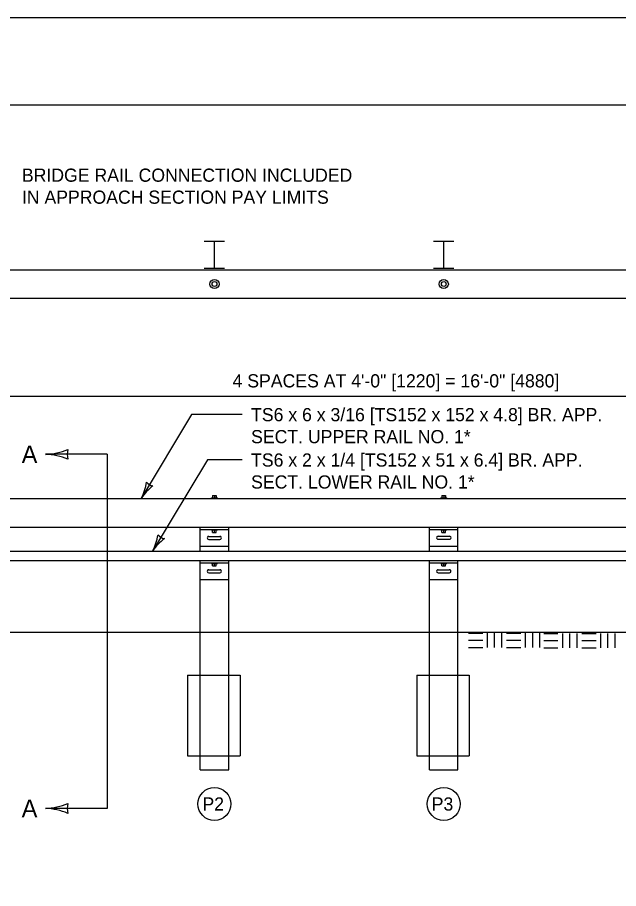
# Model space of a CAD drawing. Extents: x 49991.4 to 50021, y 49987.6 to 50011.4.
# Drawn here: x 50002.258 to 50004.991, y 49995.037 to 49998.999 of the extents above; entities that cross this region are included whole.
import ezdxf

# ---------------------------------------------------------------- set-up
doc = ezdxf.new("R2010")
doc.units = 0
for name, color, linetype in [('Level 1', 7, 'Continuous'), ('Level 2', 7, 'Continuous'), ('Level 3', 7, 'Continuous'), ('Level 4', 7, 'Continuous'), ('Level 6', 7, 'Continuous')]:
    doc.layers.add(name, color=color, linetype=linetype)

msp = doc.modelspace()

# ---------------------------------------------------------------- linework, layer by layer
at = {"layer": 'Level 1'}
for p, q in [((50003.1077, 49997.982), (50003.1991, 49997.982)), ((50003.1539, 49997.8587), (50003.1539, 49997.982)), ((50004.1503, 49997.982), (50004.2425, 49997.982)), ((50004.1964, 49997.8587), (50004.1964, 49997.982)), ((50001.743, 49997.8514), (50015.4519, 49997.8514)), ((50003.1077, 49997.8587), (50003.1991, 49997.8587)), ((50004.1503, 49997.8587), (50004.2425, 49997.8587)), ((50001.743, 49997.7218), (50015.4519, 49997.7218)), ((50002.0298, 49996.8116), (50015.4519, 49996.8116)), ((50003.1396, 49996.8144), (50003.1681, 49996.8144)), ((50003.1396, 49996.8116), (50003.1396, 49996.8144)), ((50003.1451, 49996.825), (50003.161, 49996.825)), ((50003.1451, 49996.825), (50003.1451, 49996.8144)), ((50003.1539, 49996.825), (50003.1539, 49996.8144)), ((50003.161, 49996.825), (50003.161, 49996.8144)), ((50003.1681, 49996.8116), (50003.1681, 49996.8144)), ((50004.1314, 49996.8116), (50004.2611, 49996.8116)), ((50004.1829, 49996.8144), (50004.2106, 49996.8144)), ((50004.1829, 49996.8116), (50004.1829, 49996.8144)), ((50004.1883, 49996.825), (50004.2044, 49996.825)), ((50004.1883, 49996.825), (50004.1883, 49996.8144)), ((50004.1964, 49996.825), (50004.1964, 49996.8144)), ((50004.2044, 49996.825), (50004.2044, 49996.8144)), ((50004.2106, 49996.8116), (50004.2106, 49996.8144)), ((50002.0298, 49996.6812), (50015.4519, 49996.6812)), ((50003.0882, 49996.5719), (50003.0882, 49996.6812)), ((50003.0882, 49996.6705), (50003.2188, 49996.6705)), ((50003.1396, 49996.6705), (50003.1396, 49996.6679)), ((50003.1396, 49996.6679), (50003.1681, 49996.6679)), ((50003.1451, 49996.6572), (50003.1451, 49996.6679)), ((50003.1451, 49996.6572), (50003.161, 49996.6572)), ((50003.1539, 49996.6572), (50003.1539, 49996.6679)), ((50003.161, 49996.6572), (50003.161, 49996.6679)), ((50003.1681, 49996.6705), (50003.1681, 49996.6679)), ((50003.2188, 49996.5719), (50003.2188, 49996.6812)), ((50004.1314, 49996.5719), (50004.1314, 49996.6812)), ((50004.1314, 49996.6705), (50004.2611, 49996.6705)), ((50004.1829, 49996.6705), (50004.1829, 49996.6679)), ((50004.1829, 49996.6679), (50004.2106, 49996.6679)), ((50004.1883, 49996.6572), (50004.1883, 49996.6679)), ((50004.1883, 49996.6572), (50004.2044, 49996.6572)), ((50004.1964, 49996.6572), (50004.1964, 49996.6679)), ((50004.2044, 49996.6572), (50004.2044, 49996.6679)), ((50004.2106, 49996.6705), (50004.2106, 49996.6679)), ((50004.2611, 49996.5719), (50004.2611, 49996.6812)), ((50003.127, 49996.6389), (50003.1793, 49996.6389)), ((50003.1279, 49996.6253), (50003.1785, 49996.6253)), ((50004.1714, 49996.6397), (50004.2238, 49996.6397)), ((50004.1714, 49996.6261), (50004.2221, 49996.6261)), ((50002.0449, 49996.5719), (50012.5032, 49996.5719)), ((50003.0882, 49996.595), (50003.2188, 49996.595)), ((50004.1314, 49996.595), (50004.2611, 49996.595)), ((50002.0449, 49996.5294), (50007.0485, 49996.5294)), ((50003.0882, 49996.2026), (50003.0882, 49996.5294)), ((50003.2188, 49996.2026), (50003.2188, 49996.5294)), ((50004.1314, 49996.2026), (50004.1314, 49996.5294)), ((50004.2611, 49996.2026), (50004.2611, 49996.5294)), ((50003.0882, 49996.5187), (50003.2188, 49996.5187)), ((50003.1396, 49996.5187), (50003.1396, 49996.5152)), ((50003.1396, 49996.5152), (50003.1681, 49996.5152)), ((50003.1451, 49996.5044), (50003.1451, 49996.5152)), ((50003.1451, 49996.5044), (50003.161, 49996.5044)), ((50003.1539, 49996.5044), (50003.1539, 49996.5152)), ((50003.161, 49996.5044), (50003.161, 49996.5152)), ((50003.1681, 49996.5187), (50003.1681, 49996.5152)), ((50004.1314, 49996.5187), (50004.2611, 49996.5187)), ((50004.1829, 49996.5187), (50004.1829, 49996.5152)), ((50004.1829, 49996.5152), (50004.2106, 49996.5152)), ((50004.1883, 49996.5044), (50004.1883, 49996.5152)), ((50004.1883, 49996.5044), (50004.2044, 49996.5044)), ((50004.1964, 49996.5044), (50004.1964, 49996.5152)), ((50004.2044, 49996.5044), (50004.2044, 49996.5152)), ((50004.2106, 49996.5187), (50004.2106, 49996.5152)), ((50003.127, 49996.4868), (50003.1793, 49996.4868)), ((50003.1279, 49996.4732), (50003.1785, 49996.4732)), ((50004.17, 49996.4868), (50004.2224, 49996.4868)), ((50004.1714, 49996.4734), (50004.2221, 49996.4734)), ((50003.0882, 49996.4422), (50003.2188, 49996.4422)), ((50004.1314, 49996.4422), (50004.2611, 49996.4422)), ((50001.5626, 49996.2026), (50015.4519, 49996.2026)), ((50004.3084, 49996.1988), (50004.3734, 49996.1988)), ((50004.3951, 49996.1338), (50004.3951, 49996.1988)), ((50004.4276, 49996.1338), (50004.4276, 49996.1988)), ((50004.4601, 49996.1338), (50004.4601, 49996.1988)), ((50004.4817, 49996.1988), (50004.5468, 49996.1988)), ((50004.5685, 49996.1338), (50004.5685, 49996.1988)), ((50004.6009, 49996.1338), (50004.6009, 49996.1988)), ((50004.6334, 49996.1338), (50004.6334, 49996.1988)), ((50004.6508, 49996.1974), (50004.7158, 49996.1974)), ((50004.7375, 49996.1324), (50004.7375, 49996.1974)), ((50004.77, 49996.1324), (50004.77, 49996.1974)), ((50004.8025, 49996.1324), (50004.8025, 49996.1974)), ((50004.8241, 49996.1974), (50004.8892, 49996.1974)), ((50004.9109, 49996.1324), (50004.9109, 49996.1974)), ((50004.9433, 49996.1324), (50004.9433, 49996.1974)), ((50004.9758, 49996.1324), (50004.9758, 49996.1974)), ((50004.3084, 49996.1663), (50004.3734, 49996.1663)), ((50004.3084, 49996.1338), (50004.3734, 49996.1338)), ((50004.4817, 49996.1663), (50004.5468, 49996.1663)), ((50004.4817, 49996.1338), (50004.5468, 49996.1338)), ((50004.6508, 49996.1649), (50004.7158, 49996.1649)), ((50004.6508, 49996.1324), (50004.7158, 49996.1324)), ((50004.8241, 49996.1649), (50004.8892, 49996.1649)), ((50004.8241, 49996.1324), (50004.8892, 49996.1324))]:
    msp.add_line(p, q, dxfattribs=at)
msp.add_lwpolyline([(49999.3835, 49998.9992), (50016.7501, 49998.9992), (50016.7501, 49987.7988), (49999.3835, 49987.7988)], close=True, dxfattribs=at)
for centre, radius in [((50003.1539, 49997.7866), 0.0209), ((50003.1539, 49997.7866), 0.0109), ((50004.1964, 49997.7866), 0.0209), ((50004.1964, 49997.7866), 0.0109)]:
    msp.add_circle(centre, radius, dxfattribs=at)
for centre, start, end in [((50003.1275, 49996.6321), 86.0196, 273.9804), ((50003.179, 49996.6321), 266.0196, 93.9804), ((50004.1709, 49996.6329), 86.0196, 273.9804), ((50004.2226, 49996.6329), 266.0196, 93.9804), ((50003.1275, 49996.48), 86.0196, 273.9804), ((50003.179, 49996.48), 266.0196, 93.9804), ((50004.1705, 49996.48), 86.0196, 273.9804), ((50004.2221, 49996.48), 266.0196, 93.9804)]:
    msp.add_arc(centre, 0.00681, start, end, dxfattribs=at)
at = {"layer": 'Level 2'}
for centre in [(50003.1535, 49995.4216), (50004.1963, 49995.4216)]:
    msp.add_circle(centre, 0.075, dxfattribs=at)
at = {"layer": 'Level 3'}
for p, q in [((50001.5626, 49998.6017), (50014.9504, 49998.6017)), ((50002.1107, 49997.2763), (50006.2831, 49997.2763)), ((50003.0498, 49997.1925), (50002.8205, 49996.8116)), ((50003.2803, 49997.1925), (50003.0498, 49997.1925)), ((50003.1219, 49996.9863), (50002.8724, 49996.5719)), ((50003.2803, 49996.9863), (50003.1219, 49996.9863))]:
    msp.add_line(p, q, dxfattribs=at)
for centre, radius, start, end in [((50002.6152, 49996.9218), 0.233, 331.778, 351.0279), ((50002.8866, 49996.9214), 0.0548, 221.0895, 256.8119), ((50003.0061, 49996.6892), 0.2223, 126.4067, 146.5902), ((50002.6671, 49996.6821), 0.233, 331.778, 351.0279), ((50003.058, 49996.4495), 0.2223, 126.4067, 146.5902), ((50002.9386, 49996.6817), 0.0548, 221.0895, 256.8119)]:
    msp.add_arc(centre, radius, start, end, dxfattribs=at)
at = {"layer": 'Level 4'}
for p, q in [((50003.0882, 49995.5766), (50003.0882, 49996.2026)), ((50003.2188, 49995.5766), (50003.2188, 49996.2026)), ((50004.1314, 49995.5766), (50004.1314, 49996.2026)), ((50004.2611, 49995.5766), (50004.2611, 49996.2026)), ((50003.0314, 49996.0072), (50003.271, 49996.0072)), ((50003.0314, 49996.0072), (50003.0314, 49995.6414)), ((50003.271, 49996.0072), (50003.271, 49995.6414)), ((50004.0746, 49996.0072), (50004.0746, 49995.6414)), ((50004.0746, 49996.0072), (50004.3127, 49996.0072)), ((50004.3127, 49996.0072), (50004.3127, 49995.6414)), ((50003.0314, 49995.6414), (50003.271, 49995.6414)), ((50004.0746, 49995.6414), (50004.3127, 49995.6414)), ((50003.0882, 49995.5766), (50003.2188, 49995.5766)), ((50004.1314, 49995.5766), (50004.2611, 49995.5766))]:
    msp.add_line(p, q, dxfattribs=at)
at = {"layer": 'Level 6'}
for points in [[(50002.6659, 49997.012), (50002.3859, 49997.012)], [(50002.6659, 49997.012), (50002.6659, 49995.4014)], [(50002.6659, 49995.4014), (50002.3859, 49995.4014)]]:
    msp.add_lwpolyline(points, dxfattribs=at)
for centre, radius, start, end in [((50002.3706, 49997.3223), 0.3107, 272.8273, 292.0772), ((50002.3737, 49996.7158), 0.2964, 67.456, 87.6395), ((50002.5569, 49997.012), 0.073, 162.1388, 197.8612), ((50002.3706, 49995.7117), 0.3107, 272.8273, 292.0772), ((50002.5569, 49995.4014), 0.073, 162.1388, 197.8612), ((50002.3737, 49995.1052), 0.2964, 67.456, 87.6395)]:
    msp.add_arc(centre, radius, start, end, dxfattribs=at)

# ---------------------------------------------------------------- texts
at = {"layer": 'Level 2'}
for s, height, p in [('BRIDGE RAIL CONNECTION INCLUDED', 0.06, (50002.2782, 49998.2517)), ('IN APPROACH SECTION PAY LIMITS', 0.06, (50002.2782, 49998.1517)), ('4 SPACES AT 4\'-0" [1220] = 16\'-0" [4880]', 0.06, (50003.2361, 49997.3163)), ('TS6 x 6 x 3/16 [TS152 x 152 x 4.8] BR. APP. ', 0.06, (50003.3203, 49997.1625)), ('SECT. UPPER RAIL NO. 1*', 0.06, (50003.3203, 49997.0625)), ('A', 0.08, (50002.2772, 49996.972)), ('TS6 x 2 x 1/4 [TS152 x 51 x 6.4] BR. APP.', 0.06, (50003.3203, 49996.9563)), ('SECT. LOWER RAIL NO. 1*', 0.06, (50003.3203, 49996.8563)), ('A', 0.08, (50002.2772, 49995.3614)), ('P2', 0.06, (50003.099, 49995.3917)), ('P3', 0.06, (50004.1417, 49995.3917))]:
    msp.add_text(s, height=height, dxfattribs=at).set_placement(p)

doc.saveas('drawing.dxf')
